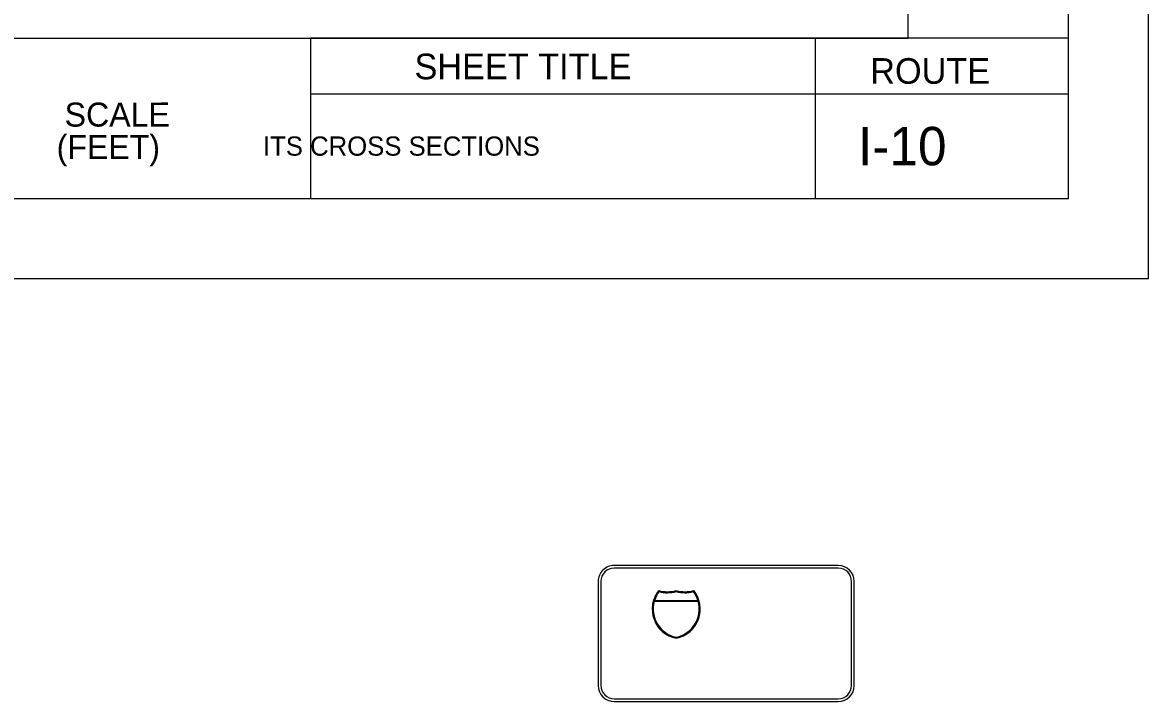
# Model space of a CAD drawing. Extents: x 2193008 to 2198143, y 1236112 to 1237864.
# Drawn here: x 2195127.5 to 2195197.9, y 1237091.6 to 1237134 of the extents above; entities that cross this region are included whole.
import ezdxf

# ---------------------------------------------------------------- set-up
doc = ezdxf.new("R2010")
doc.units = 0
for name, color, linetype in [('ANNO-SHT', 7, 'Continuous'), ('ANNO-SYMB', 7, 'Continuous'), ('ANNO-TXT', 7, 'Continuous'), ('GSOUTLINE', 7, 'Continuous'), ('Level 6', 7, 'Continuous'), ('Level 62', 7, 'Continuous'), ('SHT-BDR', 7, 'Continuous'), ('SHT-BNDRY', 7, 'Continuous')]:
    doc.layers.add(name, color=color, linetype=linetype)

msp = doc.modelspace()

# ---------------------------------------------------------------- linework, layer by layer
at = {"layer": 'ANNO-TXT'}
for p, q in [((2195145.523, 1237129.575), (2195177.051, 1237129.575)), ((2195177.051, 1237129.575), (2195192.863, 1237129.575))]:
    msp.add_line(p, q, dxfattribs=at)
at = {"layer": 'GSOUTLINE'}
for p, q in [((2195178.483, 1237100.119), (2195164.487, 1237100.119)), ((2195178.483, 1237099.953), (2195164.487, 1237099.953)), ((2195163.487, 1237099.12), (2195163.487, 1237092.623)), ((2195163.654, 1237099.12), (2195163.654, 1237092.623)), ((2195179.316, 1237092.623), (2195179.316, 1237099.12)), ((2195179.482, 1237092.623), (2195179.482, 1237099.12)), ((2195164.487, 1237091.79), (2195178.483, 1237091.79)), ((2195164.487, 1237091.623), (2195178.483, 1237091.623))]:
    msp.add_line(p, q, dxfattribs=at)
for points in [[(2195169.733, 1237097.872), (2195166.985, 1237097.872)], [(2195167.004, 1237097.934), (2195169.715, 1237097.934)]]:
    msp.add_lwpolyline(points, dxfattribs=at)
for centre, major_axis, ratio, start_param, end_param in [((2195164.487, 1237099.12), (1, 0), 0.999829, 1.570796, 3.141593), ((2195164.487, 1237099.12), (0.833, 0), 0.999829, 1.570796, 3.141593), ((2195178.483, 1237099.12), (1, 0), 0.999829, 0, 1.570796), ((2195178.483, 1237099.12), (0.833, 0), 0.999829, 0, 1.570796), ((2195168.734, 1237097.398), (1.874, 0), 0.997059, 2.472588, 4.511032), ((2195168.734, 1237097.398), (1.812, 0), 0.997059, 2.495747, 2.84029), ((2195167.811, 1237100.344), (1.874, 0), 0.997059, 4.415842, 5.008936), ((2195167.811, 1237100.344), (1.937, 0), 0.997059, 4.438241, 4.999094), ((2195168.907, 1237100.344), (1.874, 0), 0.997059, 4.415842, 5.008936), ((2195167.984, 1237097.398), (1.874, 0), 0.997059, 4.913746, 6.95219), ((2195168.907, 1237100.344), (1.937, 0), 0.997059, 4.425684, 4.986537), ((2195167.984, 1237097.398), (1.812, 0), 0.997059, 0.301302, 0.645846), ((2195168.734, 1237097.398), (1.812, 0), 0.997059, 2.876207, 4.503988), ((2195167.984, 1237097.398), (1.812, 0), 0.997059, 4.92079, 6.548571), ((2195164.487, 1237092.623), (1, 0), 0.999829, 3.141593, 4.712389), ((2195164.487, 1237092.623), (0.833, 0), 0.999829, 3.141593, 4.712389), ((2195178.483, 1237092.623), (1, 0), 0.999829, 4.712389, 6.283185), ((2195178.483, 1237092.623), (0.833, 0), 0.999829, 4.712389, 6.283185)]:
    msp.add_ellipse(centre, major_axis=major_axis, ratio=ratio, start_param=start_param, end_param=end_param, dxfattribs=at)
at = {"layer": 'Level 6'}
msp.add_line((2195192.863, 1237133.046), (2195145.523, 1237133.046), dxfattribs=at)
at = {"layer": 'Level 62'}
msp.add_lwpolyline([(2194857.863, 1237118.036), (2195197.863, 1237118.036), (2195197.863, 1237338.036), (2194857.863, 1237338.036)], close=True, dxfattribs=at)
at = {"layer": 'SHT-BDR'}
msp.add_lwpolyline([(2194882.86, 1237133.046), (2195182.86, 1237133.046), (2195182.86, 1237323.046), (2194882.86, 1237323.046)], close=True, dxfattribs=at)
at = {"layer": 'SHT-BNDRY'}
for p, q in [((2195145.523, 1237123.036), (2195145.523, 1237133.046)), ((2195177.051, 1237123.036), (2195177.051, 1237133.046))]:
    msp.add_line(p, q, dxfattribs=at)
msp.add_lwpolyline([(2194870.363, 1237123.036), (2195192.863, 1237123.036), (2195192.863, 1237333.036), (2194870.363, 1237333.036)], close=True, dxfattribs=at)

# ---------------------------------------------------------------- texts
at = {"layer": 'ANNO-SHT'}
for s, height, p in [(' I-10 ', 2.4, (2195178.827, 1237125.106)), ('          ITS CROSS SECTIONS          ', 1.2, (2195138.087, 1237125.706))]:
    msp.add_text(s, height=height, rotation=360, dxfattribs=at).set_placement(p)
at = {"layer": 'ANNO-SYMB'}
for s, p in [('SCALE', (2195130.153, 1237127.522)), ('(FEET)', (2195129.653, 1237125.493))]:
    msp.add_text(s, height=1.4994, rotation=0.0572, dxfattribs=at).set_placement(p)
at = {"layer": 'ANNO-TXT'}
for s, p in [('SHEET TITLE', (2195152.009, 1237130.478)), ('ROUTE', (2195180.482, 1237130.197))]:
    msp.add_text(s, height=1.6, dxfattribs=at).set_placement(p)

doc.saveas('drawing.dxf')
